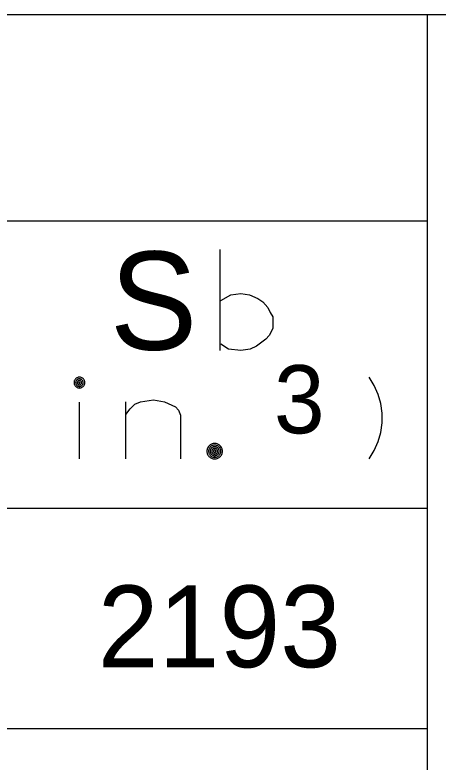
# Model space of a CAD drawing. Extents: x 635698 to 639877, y 296617 to 300175.
# Drawn here: x 639184.04 to 639199.56, y 299937.16 to 299964.57 of the extents above; entities that cross this region are included whole.
import ezdxf

# ---------------------------------------------------------------- set-up
doc = ezdxf.new("R2010")
doc.units = 0
for name, color, linetype in [('1', 7, 'Continuous'), ('2', 7, 'Continuous'), ('3', 7, 'Continuous')]:
    doc.layers.add(name, color=color, linetype=linetype)

msp = doc.modelspace()

# ---------------------------------------------------------------- linework, layer by layer
at = {"layer": '1'}
for p, q in [((639324.489, 299964.569), (639056.863, 299964.569)), ((639199.162, 299964.569), (639199.162, 299833.273)), ((639199.162, 299956.999), (639074.715, 299956.999)), ((639199.162, 299946.457), (639074.717, 299946.457)), ((639199.162, 299938.372), (639074.717, 299938.372))]:
    msp.add_line(p, q, dxfattribs=at)
at = {"layer": '2'}
for points in [[(639191.562, 299952.258), (639191.562, 299955.957)], [(639191.591, 299954.092), (639191.959, 299954.299), (639192.326, 299954.345), (639192.647, 299954.299), (639192.946, 299954.161), (639193.13, 299954.046), (639193.313, 299953.84), (639193.405, 299953.656), (639193.497, 299953.495), (639193.497, 299953.059), (639193.359, 299952.806), (639193.244, 299952.669), (639192.9, 299952.416), (639192.671, 299952.301), (639192.326, 299952.255), (639191.867, 299952.301), (639191.591, 299952.485)]]:
    msp.add_lwpolyline(points, dxfattribs=at)
at = {"layer": '3'}
for points in [[(639186.599, 299951.078), (639186.598, 299951.098), (639186.595, 299951.119), (639186.589, 299951.139), (639186.582, 299951.159), (639186.573, 299951.177), (639186.561, 299951.194), (639186.548, 299951.211), (639186.533, 299951.225), (639186.518, 299951.238), (639186.5, 299951.249), (639186.482, 299951.259), (639186.462, 299951.266), (639186.442, 299951.272), (639186.422, 299951.275), (639186.401, 299951.276), (639186.38, 299951.275), (639186.36, 299951.272), (639186.34, 299951.266), (639186.321, 299951.259), (639186.302, 299951.249), (639186.285, 299951.238), (639186.269, 299951.225), (639186.254, 299951.211), (639186.241, 299951.194), (639186.23, 299951.177), (639186.22, 299951.159), (639186.213, 299951.139), (639186.207, 299951.119), (639186.204, 299951.098), (639186.203, 299951.078), (639186.204, 299951.057), (639186.207, 299951.037), (639186.213, 299951.017), (639186.22, 299950.997), (639186.23, 299950.979), (639186.241, 299950.962), (639186.254, 299950.945), (639186.269, 299950.931), (639186.285, 299950.918), (639186.302, 299950.907), (639186.321, 299950.897), (639186.34, 299950.89), (639186.36, 299950.884), (639186.38, 299950.881), (639186.401, 299950.88), (639186.422, 299950.881), (639186.442, 299950.884), (639186.462, 299950.89), (639186.482, 299950.897), (639186.5, 299950.907), (639186.518, 299950.918), (639186.533, 299950.931), (639186.548, 299950.945), (639186.561, 299950.962), (639186.573, 299950.979), (639186.582, 299950.997), (639186.589, 299951.017), (639186.595, 299951.037), (639186.598, 299951.057), (639186.599, 299951.078)], [(639186.539, 299951.078), (639186.538, 299951.092), (639186.536, 299951.107), (639186.532, 299951.12), (639186.527, 299951.134), (639186.521, 299951.147), (639186.513, 299951.159), (639186.504, 299951.17), (639186.493, 299951.181), (639186.482, 299951.19), (639186.47, 299951.197), (639186.457, 299951.204), (639186.444, 299951.209), (639186.43, 299951.213), (639186.415, 299951.215), (639186.401, 299951.216), (639186.387, 299951.215), (639186.372, 299951.213), (639186.358, 299951.209), (639186.345, 299951.204), (639186.332, 299951.197), (639186.32, 299951.19), (639186.309, 299951.181), (639186.299, 299951.17), (639186.29, 299951.159), (639186.281, 299951.147), (639186.275, 299951.134), (639186.27, 299951.12), (639186.266, 299951.107), (639186.264, 299951.092), (639186.263, 299951.078), (639186.264, 299951.063), (639186.266, 299951.049), (639186.27, 299951.035), (639186.275, 299951.022), (639186.281, 299951.009), (639186.29, 299950.997), (639186.299, 299950.986), (639186.309, 299950.975), (639186.32, 299950.966), (639186.332, 299950.959), (639186.345, 299950.952), (639186.358, 299950.947), (639186.372, 299950.943), (639186.387, 299950.941), (639186.401, 299950.94), (639186.415, 299950.941), (639186.43, 299950.943), (639186.444, 299950.947), (639186.457, 299950.952), (639186.47, 299950.959), (639186.482, 299950.966), (639186.493, 299950.975), (639186.504, 299950.986), (639186.513, 299950.997), (639186.521, 299951.009), (639186.527, 299951.022), (639186.532, 299951.035), (639186.536, 299951.049), (639186.538, 299951.063), (639186.539, 299951.078)], [(639186.479, 299951.078), (639186.479, 299951.086), (639186.477, 299951.094), (639186.475, 299951.102), (639186.472, 299951.109), (639186.469, 299951.117), (639186.464, 299951.124), (639186.459, 299951.13), (639186.453, 299951.136), (639186.447, 299951.141), (639186.44, 299951.145), (639186.433, 299951.149), (639186.425, 299951.152), (639186.417, 299951.154), (639186.409, 299951.156), (639186.401, 299951.156), (639186.393, 299951.156), (639186.385, 299951.154), (639186.377, 299951.152), (639186.369, 299951.149), (639186.362, 299951.145), (639186.355, 299951.141), (639186.349, 299951.136), (639186.343, 299951.13), (639186.338, 299951.124), (639186.333, 299951.117), (639186.33, 299951.109), (639186.327, 299951.102), (639186.325, 299951.094), (639186.324, 299951.086), (639186.323, 299951.078), (639186.324, 299951.07), (639186.325, 299951.062), (639186.327, 299951.054), (639186.33, 299951.046), (639186.333, 299951.039), (639186.338, 299951.032), (639186.343, 299951.026), (639186.349, 299951.02), (639186.355, 299951.015), (639186.362, 299951.01), (639186.369, 299951.007), (639186.377, 299951.004), (639186.385, 299951.002), (639186.393, 299951), (639186.401, 299951), (639186.409, 299951), (639186.417, 299951.002), (639186.425, 299951.004), (639186.433, 299951.007), (639186.44, 299951.01), (639186.447, 299951.015), (639186.453, 299951.02), (639186.459, 299951.026), (639186.464, 299951.032), (639186.469, 299951.039), (639186.472, 299951.046), (639186.475, 299951.054), (639186.477, 299951.062), (639186.479, 299951.07), (639186.479, 299951.078)], [(639197.032, 299948.276), (639197.221, 299948.583), (639197.363, 299948.914), (639197.457, 299949.244), (639197.504, 299949.599), (639197.504, 299949.953), (639197.457, 299950.308), (639197.363, 299950.638), (639197.221, 299950.969), (639197.032, 299951.276)], [(639186.419, 299951.078), (639186.419, 299951.08), (639186.419, 299951.082), (639186.418, 299951.083), (639186.418, 299951.085), (639186.417, 299951.087), (639186.415, 299951.089), (639186.414, 299951.09), (639186.413, 299951.091), (639186.412, 299951.093), (639186.41, 299951.093), (639186.409, 299951.094), (639186.407, 299951.095), (639186.405, 299951.096), (639186.403, 299951.096), (639186.401, 299951.096), (639186.399, 299951.096), (639186.398, 299951.096), (639186.396, 299951.095), (639186.394, 299951.094), (639186.392, 299951.093), (639186.391, 299951.093), (639186.389, 299951.091), (639186.388, 299951.09), (639186.387, 299951.089), (639186.385, 299951.087), (639186.385, 299951.085), (639186.384, 299951.083), (639186.384, 299951.082), (639186.383, 299951.08), (639186.383, 299951.078), (639186.383, 299951.076), (639186.384, 299951.074), (639186.384, 299951.072), (639186.385, 299951.071), (639186.385, 299951.069), (639186.387, 299951.067), (639186.388, 299951.066), (639186.389, 299951.064), (639186.391, 299951.063), (639186.392, 299951.062), (639186.394, 299951.061), (639186.396, 299951.061), (639186.398, 299951.06), (639186.399, 299951.06), (639186.401, 299951.06), (639186.403, 299951.06), (639186.405, 299951.06), (639186.407, 299951.061), (639186.409, 299951.061), (639186.41, 299951.062), (639186.412, 299951.063), (639186.413, 299951.064), (639186.414, 299951.066), (639186.415, 299951.067), (639186.417, 299951.069), (639186.418, 299951.071), (639186.418, 299951.072), (639186.419, 299951.074), (639186.419, 299951.076), (639186.419, 299951.078)], [(639186.401, 299948.276), (639186.401, 299950.355)], [(639188.102, 299949.906), (639188.267, 299950.119), (639188.433, 299950.284), (639188.646, 299950.379), (639189.118, 299950.449), (639189.519, 299950.379), (639189.921, 299950.19), (639190.04, 299950.071), (639190.11, 299949.882), (639190.11, 299948.276)], [(639188.102, 299948.276), (639188.102, 299950.379)], [(639191.649, 299948.561), (639191.647, 299948.591), (639191.642, 299948.62), (639191.635, 299948.649), (639191.624, 299948.677), (639191.611, 299948.703), (639191.594, 299948.728), (639191.575, 299948.751), (639191.554, 299948.773), (639191.531, 299948.791), (639191.506, 299948.808), (639191.479, 299948.821), (639191.452, 299948.832), (639191.423, 299948.84), (639191.393, 299948.844), (639191.364, 299948.846), (639191.334, 299948.844), (639191.304, 299948.84), (639191.275, 299948.832), (639191.248, 299948.821), (639191.221, 299948.808), (639191.196, 299948.791), (639191.173, 299948.773), (639191.152, 299948.751), (639191.133, 299948.728), (639191.117, 299948.703), (639191.103, 299948.677), (639191.093, 299948.649), (639191.085, 299948.62), (639191.08, 299948.591), (639191.079, 299948.561), (639191.08, 299948.531), (639191.085, 299948.502), (639191.093, 299948.473), (639191.103, 299948.445), (639191.117, 299948.419), (639191.133, 299948.393), (639191.152, 299948.37), (639191.173, 299948.349), (639191.196, 299948.33), (639191.221, 299948.314), (639191.248, 299948.301), (639191.275, 299948.29), (639191.304, 299948.282), (639191.334, 299948.278), (639191.364, 299948.276), (639191.393, 299948.278), (639191.423, 299948.282), (639191.452, 299948.29), (639191.479, 299948.301), (639191.506, 299948.314), (639191.531, 299948.33), (639191.554, 299948.349), (639191.575, 299948.37), (639191.594, 299948.393), (639191.611, 299948.419), (639191.624, 299948.445), (639191.635, 299948.473), (639191.642, 299948.502), (639191.647, 299948.531), (639191.649, 299948.561)], [(639191.589, 299948.561), (639191.587, 299948.584), (639191.584, 299948.608), (639191.578, 299948.631), (639191.569, 299948.653), (639191.559, 299948.673), (639191.546, 299948.693), (639191.531, 299948.712), (639191.514, 299948.728), (639191.496, 299948.743), (639191.476, 299948.756), (639191.455, 299948.766), (639191.433, 299948.775), (639191.41, 299948.781), (639191.387, 299948.785), (639191.364, 299948.786), (639191.34, 299948.785), (639191.317, 299948.781), (639191.294, 299948.775), (639191.272, 299948.766), (639191.251, 299948.756), (639191.232, 299948.743), (639191.213, 299948.728), (639191.196, 299948.712), (639191.182, 299948.693), (639191.169, 299948.673), (639191.158, 299948.653), (639191.149, 299948.631), (639191.144, 299948.608), (639191.14, 299948.584), (639191.139, 299948.561), (639191.14, 299948.538), (639191.144, 299948.514), (639191.149, 299948.491), (639191.158, 299948.469), (639191.169, 299948.449), (639191.182, 299948.429), (639191.196, 299948.41), (639191.213, 299948.394), (639191.232, 299948.379), (639191.251, 299948.366), (639191.272, 299948.355), (639191.294, 299948.347), (639191.317, 299948.341), (639191.34, 299948.337), (639191.364, 299948.336), (639191.387, 299948.337), (639191.41, 299948.341), (639191.433, 299948.347), (639191.455, 299948.355), (639191.476, 299948.366), (639191.496, 299948.379), (639191.514, 299948.394), (639191.531, 299948.41), (639191.546, 299948.429), (639191.559, 299948.449), (639191.569, 299948.469), (639191.578, 299948.491), (639191.584, 299948.514), (639191.587, 299948.538), (639191.589, 299948.561)], [(639191.529, 299948.561), (639191.528, 299948.578), (639191.525, 299948.595), (639191.52, 299948.612), (639191.514, 299948.628), (639191.507, 299948.643), (639191.497, 299948.658), (639191.486, 299948.671), (639191.474, 299948.684), (639191.461, 299948.694), (639191.446, 299948.704), (639191.431, 299948.712), (639191.415, 299948.718), (639191.398, 299948.722), (639191.381, 299948.725), (639191.364, 299948.726), (639191.347, 299948.725), (639191.329, 299948.722), (639191.313, 299948.718), (639191.296, 299948.712), (639191.281, 299948.704), (639191.267, 299948.694), (639191.253, 299948.684), (639191.241, 299948.671), (639191.23, 299948.658), (639191.221, 299948.643), (639191.213, 299948.628), (639191.207, 299948.612), (639191.202, 299948.595), (639191.2, 299948.578), (639191.199, 299948.561), (639191.2, 299948.544), (639191.202, 299948.527), (639191.207, 299948.51), (639191.213, 299948.494), (639191.221, 299948.478), (639191.23, 299948.464), (639191.241, 299948.45), (639191.253, 299948.438), (639191.267, 299948.427), (639191.281, 299948.418), (639191.296, 299948.41), (639191.313, 299948.404), (639191.329, 299948.399), (639191.347, 299948.397), (639191.364, 299948.396), (639191.381, 299948.397), (639191.398, 299948.399), (639191.415, 299948.404), (639191.431, 299948.41), (639191.446, 299948.418), (639191.461, 299948.427), (639191.474, 299948.438), (639191.486, 299948.45), (639191.497, 299948.464), (639191.507, 299948.478), (639191.514, 299948.494), (639191.52, 299948.51), (639191.525, 299948.527), (639191.528, 299948.544), (639191.529, 299948.561)], [(639191.468, 299948.561), (639191.468, 299948.572), (639191.466, 299948.583), (639191.463, 299948.593), (639191.46, 299948.603), (639191.455, 299948.613), (639191.449, 299948.623), (639191.442, 299948.631), (639191.434, 299948.639), (639191.425, 299948.646), (639191.416, 299948.652), (639191.406, 299948.657), (639191.396, 299948.661), (639191.385, 299948.664), (639191.375, 299948.665), (639191.364, 299948.666), (639191.353, 299948.665), (639191.342, 299948.664), (639191.331, 299948.661), (639191.321, 299948.657), (639191.311, 299948.652), (639191.302, 299948.646), (639191.293, 299948.639), (639191.286, 299948.631), (639191.279, 299948.623), (639191.273, 299948.613), (639191.268, 299948.603), (639191.264, 299948.593), (639191.261, 299948.583), (639191.259, 299948.572), (639191.259, 299948.561), (639191.259, 299948.55), (639191.261, 299948.539), (639191.264, 299948.528), (639191.268, 299948.518), (639191.273, 299948.508), (639191.279, 299948.499), (639191.286, 299948.491), (639191.293, 299948.483), (639191.302, 299948.476), (639191.311, 299948.47), (639191.321, 299948.465), (639191.331, 299948.461), (639191.342, 299948.458), (639191.353, 299948.457), (639191.364, 299948.456), (639191.375, 299948.457), (639191.385, 299948.458), (639191.396, 299948.461), (639191.406, 299948.465), (639191.416, 299948.47), (639191.425, 299948.476), (639191.434, 299948.483), (639191.442, 299948.491), (639191.449, 299948.499), (639191.455, 299948.508), (639191.46, 299948.518), (639191.463, 299948.528), (639191.466, 299948.539), (639191.468, 299948.55), (639191.468, 299948.561)], [(639191.409, 299948.561), (639191.408, 299948.566), (639191.408, 299948.57), (639191.407, 299948.575), (639191.405, 299948.579), (639191.403, 299948.583), (639191.4, 299948.587), (639191.397, 299948.591), (639191.394, 299948.594), (639191.39, 299948.597), (639191.386, 299948.6), (639191.382, 299948.602), (639191.378, 299948.604), (639191.373, 299948.605), (639191.368, 299948.606), (639191.364, 299948.606), (639191.359, 299948.606), (639191.354, 299948.605), (639191.35, 299948.604), (639191.345, 299948.602), (639191.341, 299948.6), (639191.337, 299948.597), (639191.334, 299948.594), (639191.33, 299948.591), (639191.327, 299948.587), (639191.325, 299948.583), (639191.322, 299948.579), (639191.321, 299948.575), (639191.32, 299948.57), (639191.319, 299948.566), (639191.319, 299948.561), (639191.319, 299948.556), (639191.32, 299948.551), (639191.321, 299948.547), (639191.322, 299948.543), (639191.325, 299948.538), (639191.327, 299948.535), (639191.33, 299948.531), (639191.334, 299948.527), (639191.337, 299948.524), (639191.341, 299948.522), (639191.345, 299948.52), (639191.35, 299948.518), (639191.354, 299948.517), (639191.359, 299948.516), (639191.364, 299948.516), (639191.368, 299948.516), (639191.373, 299948.517), (639191.378, 299948.518), (639191.382, 299948.52), (639191.386, 299948.522), (639191.39, 299948.524), (639191.394, 299948.527), (639191.397, 299948.531), (639191.4, 299948.535), (639191.403, 299948.538), (639191.405, 299948.543), (639191.407, 299948.547), (639191.408, 299948.551), (639191.408, 299948.556), (639191.409, 299948.561)]]:
    msp.add_lwpolyline(points, dxfattribs=at)

# ---------------------------------------------------------------- texts
at = {"layer": '1'}
msp.add_text('2193', height=3, dxfattribs=at).set_placement((639187.074, 299940.634))
at = {"layer": '2'}
msp.add_text('S', height=3.6, dxfattribs=at).set_placement((639187.516, 299952.285))
at = {"layer": '3'}
msp.add_text('3', height=2.5, dxfattribs=at).set_placement((639193.539, 299949.217))

doc.saveas('drawing.dxf')
